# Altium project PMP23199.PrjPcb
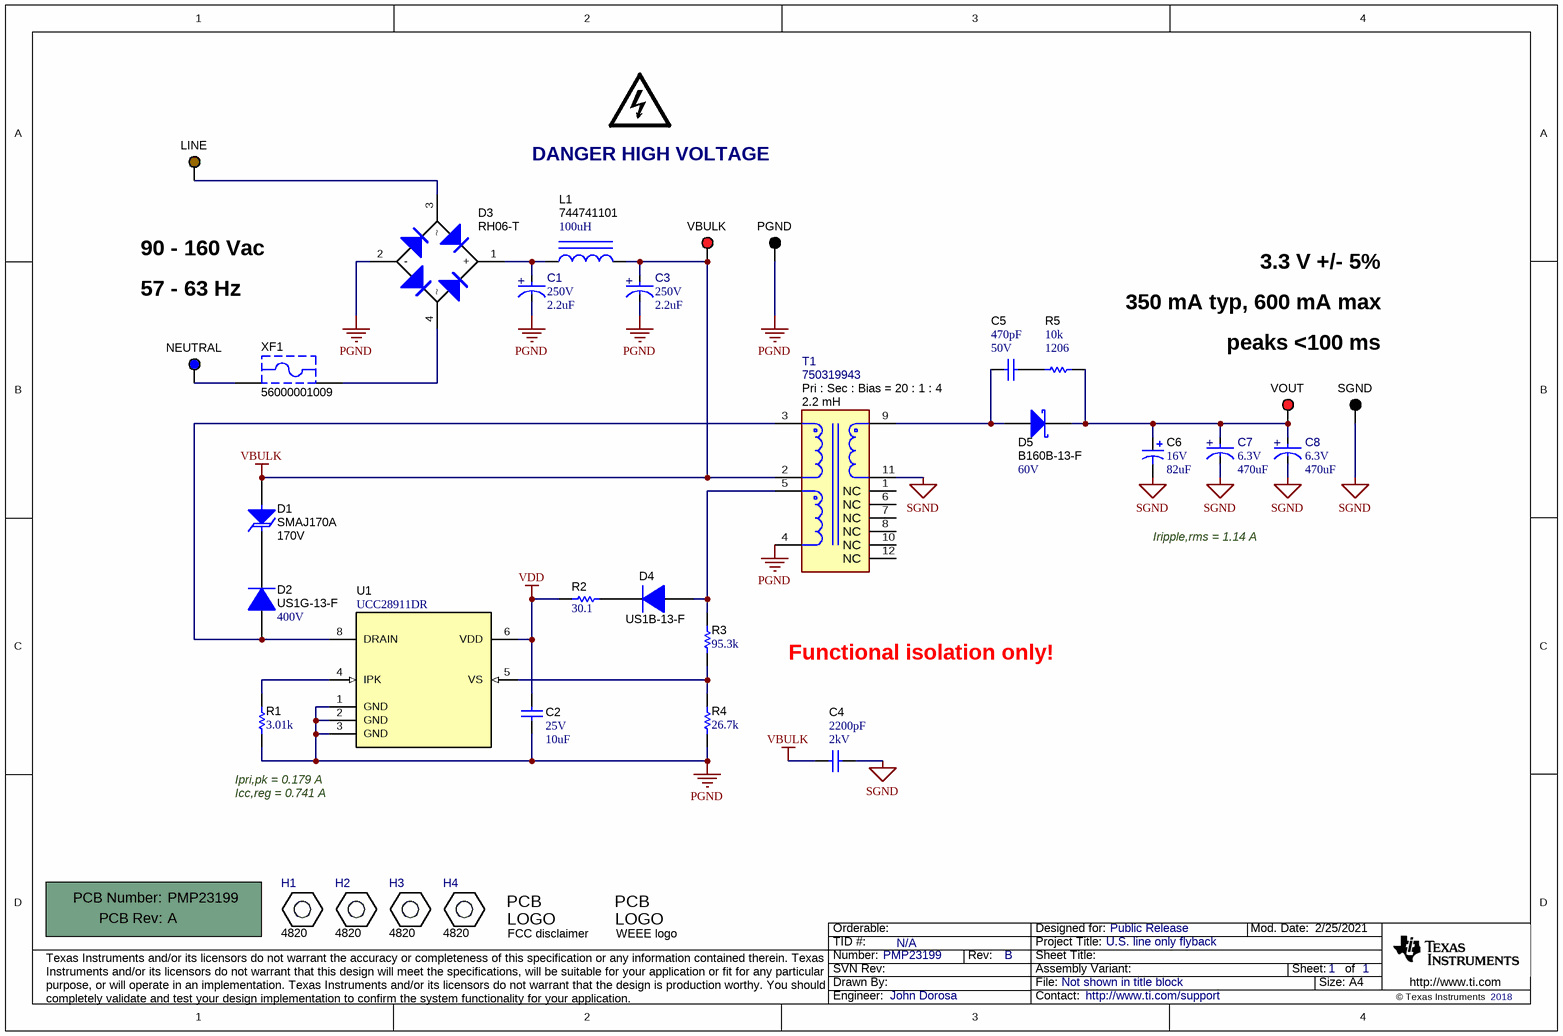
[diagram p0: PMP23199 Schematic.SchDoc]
TID: N/A; TechSupport: http://www.ti.com/support; SCH_Rev: B; PRJ_Title: U.S. line only flyback; PRJ_Number: PMP23199; PRJ_Engineer: John Dorosa; PRJ_Customer: Public Release; PCB_Rev: A; PCB_Layout: John Dorosa; CopyrightYear: 2018
1 sheet, 36 parts. Net scope: global (net labels, ports and power ports of the same name join across sheets).
Board file: PMP23199.PcbDoc

## Sheet PMP23199 Schematic.SchDoc
size A4; Date: Not shown in title block; ApprovedBy: Not shown in title block; CheckedBy: Not shown in title block; Author: Not shown in title block; CompanyName: Not shown in title block; Engineer: Not shown in title block; Organization: Not shown in title block; Address1: Not shown in title block; Address2: Not shown in title block; Address3: Not shown in title block; Address4: Not shown in title block; DocumentNumber: 1; Revision: Use project parameter SCH_Rev; SheetNumber: 1; SheetTotal: 1; PageSetup: Record=PageOptions¦CenterHorizontal=True¦CenterVertical=True¦PrintScale=1.00¦XCorrection=1.00¦YCorrection=1.00¦PrintKind=0¦BorderSize=5000000¦LeftOffset=0¦BottomOffset=0¦Orientation=2¦PaperLength=1000¦PaperWidth=1000¦Scale=100¦PaperSource=15¦PrintQuality=600¦MediaType=1¦DitherType=10¦PaperKind=Letter¦PrintScaleMode=1

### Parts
!PCB1  Printed Circuit Board  (value not drawn)  (mechanical)
C1  VDC_V: 250V  ValueDisplayed: 2.2uF  [FP-250PX2R2MEFC6.3X11_RADIAL-MFG]  (hidden comment: 250PX2R2MEFC6.3X11)
C2  VDC_V: 25V  ValueDisplayed: 10uF  [1206_180M]  (hidden comment: GRM31CR71E106KA12L)
C3  VDC_V: 250V  ValueDisplayed: 2.2uF  [FP-250PX2R2MEFC6.3X11_RADIAL-MFG]  (hidden comment: 250PX2R2MEFC6.3X11)
C4  VDC_V: 2kV  ValueDisplayed: 2200pF  [1812_HV]  (hidden comment: C4532X7R3D222K130KA)
C5  Cap_F: 470pF  VDC_V: 50V  [0603]  (hidden comment: GRM188R71H471KA01D)
C6  VDC_V: 16V  ValueDisplayed: 82uF  [WCAP-PSLP_630x580]  (hidden comment: 875105344009)
C7  VDC_V: 6.3V  ValueDisplayed: 470uF  [FP-6.3ZLH470MEFC6.3X11_RADIAL-MFG]  (hidden comment: 6.3ZLH470MEFC6.3X11)
C8  VDC_V: 6.3V  ValueDisplayed: 470uF  [FP-6.3ZLH470MEFC6.3X11_RADIAL-MFG]  (hidden comment: 6.3ZLH470MEFC6.3X11)
D1  SMAJ170A  value 170V  [SMA]
D2  US1G-13-F  value 400V  [SMA]
D3  RH06-T  [MiniDIP]
D4  US1B-13-F  [SMA]
D5  B160B-13-F  value 60V  [SMB]
H1  4820  [KEYSTONE_4820]
H2  4820  [KEYSTONE_4820]
H3  4820  [KEYSTONE_4820]
H4  4820  [KEYSTONE_4820]
L1  744741101  ValueDisplayed: 100uH  [WE-TI_8055]
LINE  5125  [Keystone5125]  (value not drawn)
Logo1  FCC disclaimer  [FCC_disclaimer]  (no BOM)
LOGO2  DANGER HIGH VOLTAGE  [IEC_HighVoltage_Small]  (no BOM)
Logo3  WEEE logo  [WEEE_Minimum]  (no BOM)
NEUTRAL  5127  [Keystone5127]  (value not drawn)
PGND  5011  [Keystone5011]  (value not drawn)
R1  ValueDisplayed: 3.01k  [0603]  (hidden comment: CRCW06033K01FKEA)
R2  ValueDisplayed: 30.1  [0603]  (hidden comment: CRCW060330R1FKEA)
R3  ValueDisplayed: 95.3k  [0603]  (hidden comment: CRCW060395K3FKEA)
R4  ValueDisplayed: 26.7k  [0603]  (hidden comment: CRCW060326K7FKEA)
R5  ValueDisplayed: 10k  [1206]  (hidden comment: CRCW120610K0JNEA)
SGND  5011  [Keystone5011]  (value not drawn)
T1  750319943  [FP-750319943_SMT12_12MM85_12MM95-MFG]
U1  UCC28911DR  [D0007A_N]
VBULK  5010  [Keystone5010]  (value not drawn)
VOUT  5010  [Keystone5010]  (value not drawn)
XF1  56000001009  [FuseHolder_560000010]

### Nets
PGND: C1.1(CATHODE) C2.2 C3.1(CATHODE) D3.2(-) PGND.1 R1.1 R4.1 T1.4 U1.1(GND) U1.2(GND) U1.3(GND)
SGND: C4.1 C6.2(-) C7.1(CATHODE) C8.1(CATHODE) SGND.1 T1.11
VBULK: C3.2(ANODE) C4.2 D1.2(A) L1.2 T1.2 VBULK.1
VDD: C2.1 R2.1 U1.6(VDD)
NetC1_2: C1.2(ANODE) D3.1(+) L1.1
NetC5_1: C5.1 R5.1
NetC5_2: C5.2 D5.2(A) T1.9
NetC6_1: C6.1(+) C7.2(ANODE) C8.2(ANODE) D5.1(K) R5.2 VOUT.1
NetD1_1: D1.1(K) D2.1(K)
NetD2_2: D2.2(A) T1.3 U1.8(DRAIN)
NetD3_3: D3.3 LINE.1
NetD3_4: D3.4 XF1.1
NetD4_1: D4.1(K) R2.2
NetD4_2: D4.2(A) R3.2 T1.5
NetNEUTRAL_1: NEUTRAL.1 XF1.2
NetR1_2: R1.2 U1.4(IPK)
NetR3_1: R3.1 R4.2 U1.5(VS)

Not connected (* = marked no-connect by the designer): T1 1(NC) 6(NC) 7(NC) 8(NC) 10(NC) 12(NC)

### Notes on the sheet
- 90 - 160 Vac
- 57 - 63 Hz
- 3.3 V +/- 5%
- 350 mA typ, 600 mA max
- peaks <100 ms
- Pri : Sec : Bias = 20 : 1 : 4
- (near T1) 2.2 mH
- Iripple,rms = 1.14 A
- Functional isolation only!
- Ipri,pk = 0.179 A
- Icc,reg = 0.741 A

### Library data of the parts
!PCB1 = CMP-0003618-2: Manufacturer: Any; PartNumber: PMP23199
C1 C3 = CMP-0094367-1: 2.2 µF 250 V Aluminum Electrolytic Capacitors Radial, Can - 1000 Hrs @ 105°C; Manufacturer: Rubycon; Dissipation Factor: 20%; AEC Qualified: No; Leakage Current: 55uA; Life: 1000Hours; SizeZ_mm: 13mm; Value: 2.2µF; IRMS_A: 30mA
C2 = CMP-0008965-2: CAP, CERM, 10 uF, 25 V, +/- 10%, X7R, 1206; Manufacturer: MuRata; TaMin_C: -55°C; Polarized: N; SizeAreaWB_mm2: 10.92; Value1: Unknown; U/M: EA; Value: 10uF; TaMax_C: 125°C; SizeZ_mm: 1.8; SizeX_mm: 3.2; SizeY_mm: 1.6; Cap_Case: 2220; SizeArea_mm2: 5.12; Cap_F: 10µF; AEC Category: Q200
C4 = CMP-0009358-2: CAP, CERM, 2200 pF, 2000 V, +/- 10%, X7R, 1812; Manufacturer: TDK; TaMin_C: -55°C; Polarized: N; SizeAreaWB_mm2: 23.1; Value1: Unknown; U/M: EA; Value: 2200pF; TaMax_C: 125°C; SizeZ_mm: 1.35; SizeX_mm: 4.5; SizeY_mm: 3.2; Cap_Case: 1812; Value2: 2000V; SizeArea_mm2: 14.4; Cap_F: 2.2nF; AEC Category: Q200
C5 = CMP-0007455-4: CAP, CERM, 470 pF, 50 V, +/- 10%, X7R, 0603; Manufacturer: MuRata; TaMin_C: -55°C; Polarized: N; SizeAreaWB_mm2: 4.68; Value1: Unknown; U/M: EA; Value: 470pF; TaMax_C: 125°C; SizeZ_mm: 1; SizeX_mm: 1.6; SizeY_mm: 0.8; SizeArea_mm2: 1.28; AEC Category: Q200
C6 = CMP-0012165-3: CAP, Aluminum Polymer, 82 uF, 16 V, +/- 20%, 0.03 ohm, D6.3xL5.8mm SMD; Manufacturer: Wurth Elektronik; TaMin_C: -55°C; ESR_ohm: 30m; Polarized: Y; Value: 82uF; TaMax_C: 105°C; Cap_Case: 6.3x5.8mm; CompType: Capacitor; AEC Qualified: N; Cap_F: 82µF; IRMS_A: 2.2A; AEC Category: Q200
C7 C8 = CMP-0094403-1: 470 µF 6.3 V Aluminum Electrolytic Capacitors Radial, Can - 6000 Hrs @ 105°C; Manufacturer: Rubycon; AEC Qualified: No; IRMS_A: 540mA; Esr: 94m; Life: 6000Hours; Cap_F: 470µF; SizeZ_mm: 12.5mm; Leakage Current: 29.61uA; Value: 470µF; Tolerance_%: 20%; Dissipation Factor: 22%
D1 = CMP-0084984-1: Diode, TVS, Uni, 170 V, 275 Vc, 400 W, 1.5 A, SMA; Manufacturer: Littelfuse; Ppk: 400W; SizeY_mm: 2.92; SizeZ_mm: 2.87; SizeAreaWB_mm2: 37.3428; Ipp: 1.5A; Vbr_Min: 189V; AEC Category: Q101; RJA_CperW: 120; Vbr_Max: 209V; AEC Qualified: N; SizeX_mm: 5.59; Vc: 275V; SizeArea_mm2: 16.3228
D2 = CMP-0077026-2: Diode, Ultrafast, 400 V, 1 A, SMA; Manufacturer: Diodes Inc.; SizeY_mm: 2.92; Value1: 1A; SizeAreaWB_mm2: 37.3428; Value2: 1.3V; TJmax_C: 150°C; Green_REACh: Incomplete; SizeArea_mm2: 16.3228; SizeX_mm: 5.59; SizeZ_mm: 2.87; AEC Category: Q101; Green_Lifecycle: Not Set
D3 = CMP-0029221-3: Diode, Switching-Bridge, 600 V, 0.5 A, MiniDIP; Manufacturer: Diodes Inc.; AEC Category: Q101; Value: 600V; Value1: 0.5A; Value2: 1.15V; SizeX_mm: 7; Green_Lifecycle: Active; SizeAreaWB_mm2: 62.1; SizeY_mm: 4.9; Io_A: 500mA; Green_REACh: Passed; SizeArea_mm2: 34.3; SizeZ_mm: 3; AEC Qualified: N; TJmax_C: 150°C
D4 = CMP-0076888-2: Diode, Ultrafast, 100 V, 1 A, SMA; Manufacturer: Diodes Inc.; Value2: 1V; SizeX_mm: 5.59; TJmax_C: 150°C; Green_REACh: Incomplete; Vr_V: 100V; RJC_CperW: 30.0; SizeArea_mm2: 16.3228; SizeZ_mm: 2.87; Value1: 1A; Green_Lifecycle: Not Set; AEC Category: Q101; SizeY_mm: 2.92; SizeAreaWB_mm2: 37.3428; Value: 100V
D5 = CMP-0028390-2: Diode, Schottky, 60 V, 1 A, SMB; Manufacturer: Diodes Inc.; TJmax_C: 150°C; SizeAreaWB_mm2: 44.156; SizeX_mm: 5.6; Vf_V: 700mV; Green_REACh: Passed; SizeArea_mm2: 21.336; SizeY_mm: 3.81; AEC Category: Q101; Value1: 1A; SizeZ_mm: 2.6; Green_Lifecycle: Active; RJC_CperW: 20; Value2: 0.7V
H1-H4 = CMP-0003652-1: Manufacturer: Keystone; CompType: Standoff
L1 = CMP-0064515-2: Inductor, Wirewound, Ferrite, 100 uH, 1.1 A, 0.39 ohm, TH; Manufacturer: Wurth Elektronik; Isat: 0.9A @ 10% inductance drop; Irms: 1.1A @ 40C rise; Green_Lifecycle: Active; SizeAreaWB_mm2: 110.25; DCR_ohm: 0.39; Green_REACh: Passed; Value: 100uH; Imax_A: 1.1A; SizeZ_mm: 6; SizeX_mm: 8.5; SizeArea_mm2: 72.25; Ind_H: 100µH; AEC Category: Q200
LINE = CMP-0055157-1: Test Point, Multipurpose, Brown, TH; Manufacturer: Keystone; CNHeader: FALSE; Green_Lifecycle: Active; Green_REACh: Passed; ContactFinish: Silver; CT: TRUE
Logo1 = CMP-0074847-1: FCC_disclaimer; Library Reference: Logo
LOGO2 = CMP-0074835-1: IEC 61010-1 High Voltage Warning; SymbolCreator: a0412235
Logo3 = CMP-0074769-1
NEUTRAL = CMP-0055156-1: Test Point, Multipurpose, Blue, TH; Manufacturer: Keystone; CNHeader: FALSE; Green_Lifecycle: Active; Green_REACh: Passed; ContactFinish: Silver; CT: TRUE
PGND SGND = CMP-0055148-1: Test Point, Multipurpose, Black, TH; Manufacturer: Keystone; CNHeader: FALSE; Green_Lifecycle: Active; Green_REACh: Passed; ContactFinish: Silver; CT: TRUE
R1 = CMP-0022371-4: RES, 3.01 k, 1%, 0.1 W, AEC-Q200 Grade 0, 0603; Manufacturer: Vishay-Dale; Power_W: 100mW; TempCo: 100 ppm/C; Value_Code: 3k01; Value: 3.01k; EIA_Code: E96; SizeX_mm: 1.6; SizeY_mm: 0.8; SizeZ_mm: 1; Value2: 0.1W; SizeArea_mm2: 1.28; AEC Qualified: Y; VDC_V: 75V; AEC Category: Q200; AEC Grade: 0
R2 = CMP-0022326-4: RES, 30.1, 1%, 0.1 W, AEC-Q200 Grade 0, 0603; Manufacturer: Vishay-Dale; Power_W: 100mW; TempCo: 100 ppm/C; Value_Code: 30R1; Value: 30.1; EIA_Code: E96; SizeX_mm: 1.6; SizeY_mm: 0.8; SizeZ_mm: 1; Value2: 0.1W; SizeArea_mm2: 1.28; AEC Qualified: Y; VDC_V: 75V; AEC Category: Q200; AEC Grade: 0
R3 = CMP-0022659-4: RES, 95.3 k, 1%, 0.1 W, AEC-Q200 Grade 0, 0603; Manufacturer: Vishay-Dale; Power_W: 100mW; TempCo: 100 ppm/C; Value_Code: 95k3; Value: 95.3k; EIA_Code: E96; SizeX_mm: 1.6; SizeY_mm: 0.8; SizeZ_mm: 1; Value2: 0.1W; SizeArea_mm2: 1.28; AEC Qualified: Y; VDC_V: 75V; AEC Category: Q200; AEC Grade: 0
R4 = CMP-0022249-4: RES, 26.7 k, 1%, 0.1 W, AEC-Q200 Grade 0, 0603; Manufacturer: Vishay-Dale; Power_W: 100mW; TempCo: 100 ppm/C; Value_Code: 26k7; Value: 26.7k; EIA_Code: E96; SizeX_mm: 1.6; SizeY_mm: 0.8; SizeZ_mm: 1; Value2: 0.1W; SizeArea_mm2: 1.28; AEC Qualified: Y; VDC_V: 75V; AEC Category: Q200; AEC Grade: 0
R5 = CMP-0018576-3: RES, 10 k, 5%, 0.25 W, AEC-Q200 Grade 0, 1206; Manufacturer: Vishay-Dale; Power_W: 250mW; TempCo: 200 ppm/C; Value_Code: 10k0; Value: 10k; EIA_Code: E24; SizeX_mm: 3.2; SizeY_mm: 1.6; SizeZ_mm: 1.35; Value2: 0.25W; SizeArea_mm2: 5.12; AEC Qualified: Y; VDC_V: 200V; AEC Category: Q200; AEC Grade: 0
T1 = CMP-0094334-1: TRANSFORMER; Manufacturer: Wurth; Ns1toNp: 4:1/20:1; SizeZ_mm: 6.35mm; AEC Qualified: No; DCR_ohm: 6; Voltage_Isolation_Vrms: 1.25kV; Frequency_Fixed: 110kHz; Ind_H: 2.2mH; Rsec1_ohm: 35m
U1 = CMP-0074093-2: 700V Flyback Switcher with Constant-Voltage Constant-Current and Primary-side Regulation, D0007A (SOIC-7); Alternate Manufacturer: Texas Instruments; SizeAreaWB_mm2: 55.2; U/M: EA; SizeZ_mm: 1.75; SizeX_mm: 6.0; SizeY_mm: 4.9; SizeArea_mm2: 29.4; CompType: IC; AEC Category: Q200; AEC Qualified: N
VBULK VOUT = CMP-0055147-1: Test Point, Multipurpose, Red, TH; Manufacturer: Keystone; CNHeader: FALSE; Green_Lifecycle: Active; Green_REACh: Passed; ContactFinish: Silver; CT: TRUE
XF1 = CMP-0003627-1: Fuse Holder, TR5, TH; Manufacturer: Littelfuse

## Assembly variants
001: not fitted C5 H1 H2 H3 H4 R5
